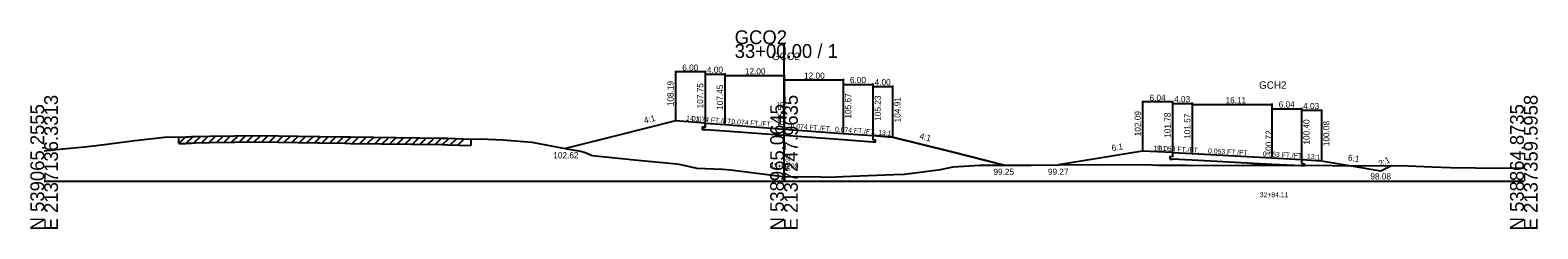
# Model space of a CAD drawing. Extents: x -14327 to 8886, y -10 to 39048.
# Drawn here: x 997.2 to 1302.8, y 5990.3 to 6030.6 of the extents above; entities that cross this region are included whole.
import ezdxf

# ---------------------------------------------------------------- set-up
doc = ezdxf.new("R2010")
doc.units = 0
for name, color, linetype in [('Level 20', 7, 'Continuous'), ('Level 5', 7, 'Continuous'), ('Level 53', 7, 'Continuous'), ('Level 54', 7, 'Continuous'), ('Level 55', 7, 'Continuous'), ('Level 7', 7, 'Continuous'), ('RD_GPK_XS_Cell', 7, 'Continuous'), ('RD_XS_EwShp', 7, 'Continuous'), ('RD_XS_ExGround', 7, 'Continuous'), ('RD_XS_ExPaveRet', 7, 'Continuous'), ('RD_XS_Pave', 7, 'Continuous'), ('RD_XS_TX_Baseline', 7, 'Continuous'), ('RD_XS_TX_Elev_EX', 7, 'Continuous'), ('RD_XS_TX_Elev_PR', 7, 'Continuous'), ('RD_XS_TX_Station', 7, 'Continuous')]:
    doc.layers.add(name, color=color, linetype=linetype)

msp = doc.modelspace()

# ---------------------------------------------------------------- linework, layer by layer
at = {"layer": 'Level 20'}
for p, q in [((1222.71, 6016.24), (1222.71, 6006.29)), ((1228.75, 6016.04), (1222.71, 6016.04)), ((1228.75, 6016.24), (1228.75, 6005.98)), ((1228.75, 6015.93), (1228.75, 6005.98)), ((1232.78, 6015.93), (1232.78, 6005.77)), ((1228.75, 6015.73), (1232.78, 6015.73)), ((1232.78, 6015.72), (1232.78, 6005.77)), ((1232.78, 6015.52), (1248.88, 6015.52)), ((1248.88, 6015.72), (1248.88, 6004.92)), ((1248.88, 6014.87), (1248.88, 6004.92)), ((1248.88, 6014.67), (1254.92, 6014.67)), ((1254.92, 6014.87), (1254.92, 6004.6)), ((1254.92, 6014.55), (1254.92, 6004.6)), ((1254.92, 6014.35), (1258.95, 6014.35)), ((1258.95, 6014.55), (1258.95, 6004.28)), ((1210.63, 6004.09), (1205.63, 6003.27)), ((1222.71, 6006.09), (1210.63, 6004.09)), ((1228.75, 6005.78), (1222.71, 6006.09)), ((1228.25, 6004.97), (1228.25, 6004.47)), ((1228.75, 6004.94), (1228.25, 6004.97)), ((1228.25, 6004.47), (1228.75, 6004.44)), ((1228.75, 6005.78), (1228.75, 6004.94)), ((1228.75, 6005.78), (1232.78, 6005.57)), ((1232.78, 6004.23), (1228.75, 6004.44)), ((1232.78, 6005.57), (1248.88, 6004.72)), ((1248.88, 6003.38), (1232.78, 6004.23)), ((1248.88, 6004.72), (1254.92, 6004.4)), ((1254.92, 6004.4), (1254.92, 6003.56)), ((1254.92, 6004.4), (1258.95, 6004.08)), ((1258.95, 6004.08), (1271.03, 6002.08)), ((1254.92, 6003.06), (1248.88, 6003.38)), ((1254.92, 6003.56), (1255.43, 6003.54)), ((1255.43, 6003.04), (1254.92, 6003.06)), ((1255.43, 6003.54), (1255.43, 6003.04)), ((1271.03, 6002.08), (1273.19, 6003.15))]:
    msp.add_line(p, q, dxfattribs=at)
at = {"layer": 'Level 5'}
for p, q in [((1133.5, 6010.95), (1133.5, 6010.45)), ((1134, 6010.91), (1133.5, 6010.95)), ((1133.5, 6010.45), (1134, 6010.41)), ((1134, 6011.75), (1134, 6010.91)), ((1138, 6010.12), (1134, 6010.41)), ((1150, 6009.23), (1138, 6010.12)), ((1162, 6008.34), (1150, 6009.23)), ((1168, 6007.9), (1162, 6008.34)), ((1168, 6009.23), (1168, 6008.4)), ((1168, 6008.4), (1168.5, 6008.36)), ((1168.5, 6007.86), (1168, 6007.9)), ((1168.5, 6008.36), (1168.5, 6007.86))]:
    msp.add_line(p, q, dxfattribs=at)
at = {"layer": 'Level 54'}
for p, q in [((1128, 6022.34), (1128, 6012.39)), ((1134, 6022.14), (1128, 6022.14)), ((1134, 6022.34), (1134, 6011.95)), ((1134, 6021.9), (1134, 6011.95)), ((1134, 6021.7), (1138, 6021.7)), ((1138, 6021.9), (1138, 6011.65)), ((1138, 6021.6), (1138, 6011.65)), ((1138, 6021.4), (1150, 6021.4)), ((1150, 6021.6), (1150, 6010.76)), ((1150, 6020.71), (1150, 6010.76)), ((1150, 6020.51), (1162, 6020.51)), ((1162, 6020.71), (1162, 6009.87)), ((1162, 6019.82), (1162, 6009.87)), ((1162, 6019.62), (1168, 6019.62)), ((1168, 6019.82), (1168, 6009.43)), ((1168, 6019.38), (1168, 6009.43)), ((1168, 6019.18), (1172, 6019.18)), ((1172, 6019.38), (1172, 6009.11))]:
    msp.add_line(p, q, dxfattribs=at)
at = {"layer": 'Level 7'}
for p, q in [((1128, 6012.19), (1116, 6009.19)), ((1134, 6011.75), (1128, 6012.19)), ((1116, 6009.19), (1105.7, 6006.62)), ((1168, 6009.23), (1172, 6008.91)), ((1172, 6008.91), (1184, 6005.91)), ((1184, 6005.91), (1194.65, 6003.25))]:
    msp.add_line(p, q, dxfattribs=at)
at = {"layer": 'RD_GPK_XS_Cell'}
for p, q in [((1150, 6000), (1150, 6027.77)), ((1000, 6000), (1150, 6000)), ((1150, 6000), (1300, 6000))]:
    msp.add_line(p, q, dxfattribs=at)
at = {"layer": 'RD_XS_EwShp'}
msp.add_lwpolyline([(1116, 6009.19), (1105.7, 6006.62), (1105.96, 6006.57), (1108.78, 6006.07), (1109.69, 6005.82), (1111.1, 6005.19), (1118.48, 6004.41), (1118.93, 6004.37), (1128.28, 6003.47), (1128.61, 6003.43), (1129.02, 6003.37), (1132.32, 6002.59), (1137.52, 6002.44), (1139.22, 6002.31), (1140.24, 6002.17), (1149.26, 6000.97), (1150, 6000.96), (1157.47, 6000.86), (1159.09, 6000.77), (1161.9, 6000.96), (1172.26, 6001.34), (1174.41, 6001.43), (1181.72, 6002.35), (1184.28, 6002.86), (1189.73, 6003.24), (1194.65, 6003.25), (1184, 6005.91), (1172, 6008.91), (1168, 6009.23), (1168, 6008.4), (1168.5, 6008.36), (1168.5, 6007.86), (1168, 6007.9), (1162, 6008.34), (1150, 6009.23), (1138, 6010.12), (1134, 6010.41), (1133.5, 6010.45), (1133.5, 6010.95), (1134, 6010.91), (1134, 6011.75), (1128, 6012.19)], close=True, dxfattribs=at)
at = {"layer": 'RD_XS_ExGround'}
for p, q in [((1003.77, 6006.53), (1008.19, 6006.93)), ((1008.19, 6006.93), (1011.68, 6007.37)), ((1011.68, 6007.37), (1018.35, 6008.25)), ((1018.35, 6008.25), (1020.82, 6008.53)), ((1020.82, 6008.53), (1024.4, 6008.88)), ((1024.4, 6008.88), (1026.28, 6008.96)), ((1026.28, 6008.96), (1027.29, 6008.93)), ((1027.29, 6008.93), (1028.73, 6008.95)), ((1028.73, 6008.95), (1029.22, 6008.97)), ((1029.22, 6008.97), (1029.85, 6009.01)), ((1029.85, 6009.01), (1030.64, 6009.03)), ((1030.64, 6009.03), (1033.59, 6009.09)), ((1033.59, 6009.09), (1043.58, 6009.26)), ((1043.58, 6009.26), (1055.39, 6009.05)), ((1055.39, 6009.05), (1055.92, 6009.04)), ((1055.92, 6009.04), (1060.99, 6008.97)), ((1060.99, 6008.97), (1062.14, 6008.95)), ((1062.14, 6008.95), (1080.66, 6008.71)), ((1080.66, 6008.71), (1081.86, 6008.67)), ((1081.86, 6008.67), (1086.52, 6008.5)), ((1086.52, 6008.5), (1088.46, 6008.55)), ((1088.46, 6008.55), (1093, 6008.38)), ((1093, 6008.38), (1098.88, 6007.86)), ((1098.88, 6007.86), (1105.96, 6006.57)), ((1000, 6006.11), (1003.77, 6006.53)), ((1105.96, 6006.57), (1108.78, 6006.07)), ((1108.78, 6006.07), (1109.69, 6005.82)), ((1109.69, 6005.82), (1111.1, 6005.19)), ((1111.1, 6005.19), (1118.48, 6004.41)), ((1118.48, 6004.41), (1118.93, 6004.37)), ((1118.93, 6004.37), (1128.28, 6003.47)), ((1128.28, 6003.47), (1128.61, 6003.43)), ((1128.61, 6003.43), (1129.02, 6003.37)), ((1129.02, 6003.37), (1132.32, 6002.59)), ((1132.32, 6002.59), (1137.52, 6002.44)), ((1137.52, 6002.44), (1139.22, 6002.31)), ((1139.22, 6002.31), (1140.24, 6002.17)), ((1140.24, 6002.17), (1149.26, 6000.97)), ((1149.26, 6000.97), (1150, 6000.96)), ((1150, 6000.96), (1157.47, 6000.86)), ((1157.47, 6000.86), (1159.09, 6000.77)), ((1159.09, 6000.77), (1161.9, 6000.96)), ((1161.9, 6000.96), (1172.26, 6001.34)), ((1172.26, 6001.34), (1174.41, 6001.43)), ((1174.41, 6001.43), (1181.72, 6002.35)), ((1181.72, 6002.35), (1184.28, 6002.86)), ((1184.28, 6002.86), (1189.73, 6003.24)), ((1189.73, 6003.24), (1200.09, 6003.25)), ((1200.09, 6003.25), (1205.73, 6003.27)), ((1205.73, 6003.27), (1214.74, 6003.35)), ((1214.74, 6003.35), (1224.57, 6003.27)), ((1224.57, 6003.27), (1225.77, 6003.25)), ((1225.77, 6003.25), (1231.61, 6003.22)), ((1231.61, 6003.22), (1243.06, 6003.18)), ((1243.06, 6003.18), (1244.54, 6003.22)), ((1244.54, 6003.22), (1246.47, 6003.21)), ((1246.47, 6003.21), (1261.11, 6003.18)), ((1261.11, 6003.18), (1267.26, 6003.12)), ((1267.26, 6003.12), (1274.95, 6003.15)), ((1274.95, 6003.15), (1281.39, 6002.86)), ((1281.39, 6002.86), (1285.11, 6002.77)), ((1285.11, 6002.77), (1290.21, 6002.7)), ((1290.21, 6002.7), (1300, 6002.64))]:
    msp.add_line(p, q, dxfattribs=at)
at = {"layer": 'RD_XS_ExPaveRet'}
for p, q in [((1027.29, 6007.63), (1028.64, 6008.95)), ((1027.29, 6007.63), (1027.29, 6008.93)), ((1027.29, 6007.63), (1028.73, 6007.65)), ((1028.73, 6007.65), (1029.22, 6007.67)), ((1028.82, 6007.66), (1030.21, 6009.02)), ((1029.22, 6007.67), (1029.85, 6007.71)), ((1029.85, 6007.71), (1030.64, 6007.73)), ((1030.35, 6007.73), (1031.7, 6009.05)), ((1030.64, 6007.73), (1033.59, 6007.79)), ((1031.88, 6007.76), (1033.23, 6009.08)), ((1033.4, 6007.78), (1034.75, 6009.11)), ((1033.59, 6007.79), (1043.58, 6007.96)), ((1034.93, 6007.81), (1036.28, 6009.13)), ((1036.46, 6007.84), (1037.81, 6009.16)), ((1037.99, 6007.86), (1039.34, 6009.18)), ((1039.52, 6007.89), (1040.87, 6009.21)), ((1041.05, 6007.91), (1042.4, 6009.24)), ((1042.58, 6007.94), (1043.91, 6009.25)), ((1043.58, 6007.96), (1055.39, 6007.75)), ((1044.1, 6007.95), (1045.41, 6009.23)), ((1045.63, 6007.92), (1046.93, 6009.2)), ((1047.16, 6007.89), (1048.46, 6009.17)), ((1048.69, 6007.87), (1049.99, 6009.15)), ((1050.22, 6007.84), (1051.52, 6009.12)), ((1051.75, 6007.82), (1053.05, 6009.09)), ((1053.27, 6007.79), (1054.58, 6009.07)), ((1054.8, 6007.76), (1056.1, 6009.04)), ((1055.39, 6007.75), (1055.92, 6007.74)), ((1055.92, 6007.74), (1060.99, 6007.67)), ((1056.33, 6007.74), (1057.64, 6009.02)), ((1057.86, 6007.71), (1059.16, 6008.99)), ((1059.39, 6007.69), (1060.69, 6008.97)), ((1060.92, 6007.67), (1062.22, 6008.95)), ((1060.99, 6007.67), (1062.14, 6007.65)), ((1062.14, 6007.65), (1080.66, 6007.41)), ((1062.44, 6007.64), (1063.75, 6008.93)), ((1063.97, 6007.62), (1065.28, 6008.91)), ((1065.5, 6007.6), (1066.81, 6008.89)), ((1067.03, 6007.58), (1068.34, 6008.87)), ((1068.56, 6007.56), (1069.87, 6008.85)), ((1070.09, 6007.54), (1071.39, 6008.83)), ((1071.62, 6007.52), (1072.92, 6008.81)), ((1073.14, 6007.5), (1074.45, 6008.79)), ((1074.67, 6007.48), (1075.98, 6008.77)), ((1076.2, 6007.46), (1077.51, 6008.75)), ((1077.73, 6007.44), (1079.04, 6008.73)), ((1079.26, 6007.42), (1080.56, 6008.71)), ((1080.66, 6007.41), (1081.86, 6007.37)), ((1080.79, 6007.4), (1082.07, 6008.66)), ((1081.86, 6007.37), (1086.52, 6007.2)), ((1082.31, 6007.35), (1083.59, 6008.6)), ((1083.84, 6007.29), (1085.12, 6008.55)), ((1086.52, 6008.5), (1086.52, 6007.2))]:
    msp.add_line(p, q, dxfattribs=at)
at = {"layer": 'RD_XS_Pave'}
for p, q in [((1134, 6011.75), (1138, 6011.45)), ((1138, 6011.45), (1150, 6010.56)), ((1150, 6010.56), (1162, 6009.67)), ((1162, 6009.67), (1168, 6009.23))]:
    msp.add_line(p, q, dxfattribs=at)

# ---------------------------------------------------------------- texts
at = {"layer": 'Level 20'}
for s, height, p in [('GCH2', 1.5, (1246.31, 6018.72)), ('GCH2', 1.5, (1246.31, 6018.72)), ('6.04', 1.25, (1224.12, 6016.29)), ('4.03', 1.25, (1229.09, 6015.98)), ('16.11', 1.25, (1239.51, 6015.77)), ('6.04', 1.25, (1250.29, 6014.92)), ('4.03', 1.25, (1255.26, 6014.6)), ('99.27', 1.25, (1203.51, 6001.27)), ('98.08', 1.25, (1268.88, 6000.33)), ('32+84.11', 1, (1246.46, 5996.72)), ('32+84.11', 1, (1246.46, 5996.72))]:
    msp.add_text(s, height=height, dxfattribs=at).set_placement(p)
for s, height, rotation, p in [('102.09', 1.25, 90, (1222.33, 6009.09)), ('101.78', 1.25, 90, (1228.37, 6008.78)), ('101.57', 1.25, 90, (1232.4, 6008.57)), (' 100.72', 1.25, 90, (1248.88, 6004.72)), (' 100.72', 1.25, 90, (1248.88, 6004.72)), ('100.40', 1.25, 90, (1256.55, 6007.4)), ('100.08', 1.25, 90, (1260.58, 6007.08)), ('6:1', 1.25, 9.4023, (1216.51, 6006.08)), ('19:1', 1, 356.9973, (1224.84, 6006.23)), ('0.053 FT./FT.', 1, 356.9778, (1225.9, 6006.18)), ('0.053 FT./FT.', 1, 356.9796, (1235.96, 6005.65)), ('0.053 FT./FT.', 1, 356.9817, (1247.04, 6005.06)), ('13:1', 1, 355.4565, (1256, 6004.56)), ('6:1', 1.25, 350.5998, (1264.28, 6004.21)), ('2:1', 1.25, 26.4116, (1270.93, 6002.87))]:
    msp.add_text(s, height=height, rotation=rotation, dxfattribs=at).set_placement(p)
at = {"layer": 'Level 53'}
for s, rotation, p in [('108.19', 90, (1127.62, 6015.19)), ('107.75', 90, (1133.62, 6014.75)), ('107.45', 90, (1137.63, 6014.45)), ('105.67', 90, (1163.63, 6012.67)), ('105.23', 90, (1169.62, 6012.23)), ('104.91', 90, (1173.62, 6011.91)), ('4:1', 14.0362, (1121.76, 6011.66)), ('4:1', 345.9638, (1177.39, 6008.59))]:
    msp.add_text(s, height=1.25, rotation=rotation, dxfattribs=at).set_placement(p)
for s, p in [('102.62', (1103.23, 6004.62)), ('99.25', (1192.46, 6001.25))]:
    msp.add_text(s, height=1.25, dxfattribs=at).set_placement(p)
at = {"layer": 'Level 54'}
for s, p in [('6.00', (1129.37, 6022.39)), ('4.00', (1134.37, 6021.95)), ('12.00', (1142.07, 6021.65)), ('12.00', (1154.07, 6020.76)), ('6.00', (1163.37, 6019.87)), ('4.00', (1168.37, 6019.43))]:
    msp.add_text(s, height=1.25, dxfattribs=at).set_placement(p)
at = {"layer": 'Level 55'}
for s, rotation, p in [('14:1', 355.7678, (1130.12, 6012.28)), ('0.074 FT./FT.', 355.7678, (1131.31, 6012.2)), ('0.074 FT./FT.', 355.7678, (1139.31, 6011.6)), ('0.074 FT./FT.', 355.7678, (1151.31, 6010.72)), ('0.074 FT./FT.', 355.7678, (1160.31, 6010.05)), ('13:1', 355.4261, (1169.07, 6009.4))]:
    msp.add_text(s, height=1, rotation=rotation, dxfattribs=at).set_placement(p)
at = {"layer": 'RD_GPK_XS_Cell'}
for s, p in [('GCO2', (1140, 6027.77)), ('33+00.00 / 1', (1140, 6024.97))]:
    msp.add_text(s, height=2.8, dxfattribs=at).set_placement(p)
for s, p in [('E 2137136.3313', (1002.8, 5990)), ('E 2137247.9635', (1152.8, 5990)), ('E 2137359.5958', (1302.8, 5990)), ('N 539065.2555', (1000, 5990)), ('N 538965.0645', (1150, 5990)), ('N 538864.8735', (1300, 5990))]:
    msp.add_text(s, height=2.8, rotation=90, dxfattribs=at).set_placement(p)
at = {"layer": 'RD_XS_TX_Baseline'}
msp.add_text('GCO2', height=1.5, dxfattribs=at).set_placement((1147.55, 6024.56))
at = {"layer": 'RD_XS_TX_Elev_EX'}
msp.add_text('96.96', height=1, rotation=90, dxfattribs=at).set_placement((1151.25, 6001.96))
at = {"layer": 'RD_XS_TX_Elev_PR'}
msp.add_text(' 106.56', height=1.25, rotation=90, dxfattribs=at).set_placement((1150, 6010.56))
at = {"layer": 'RD_XS_TX_Station'}
msp.add_text('33+00.00', height=1, dxfattribs=at).set_placement((1147.11, 6002.56))

doc.saveas('drawing.dxf')
